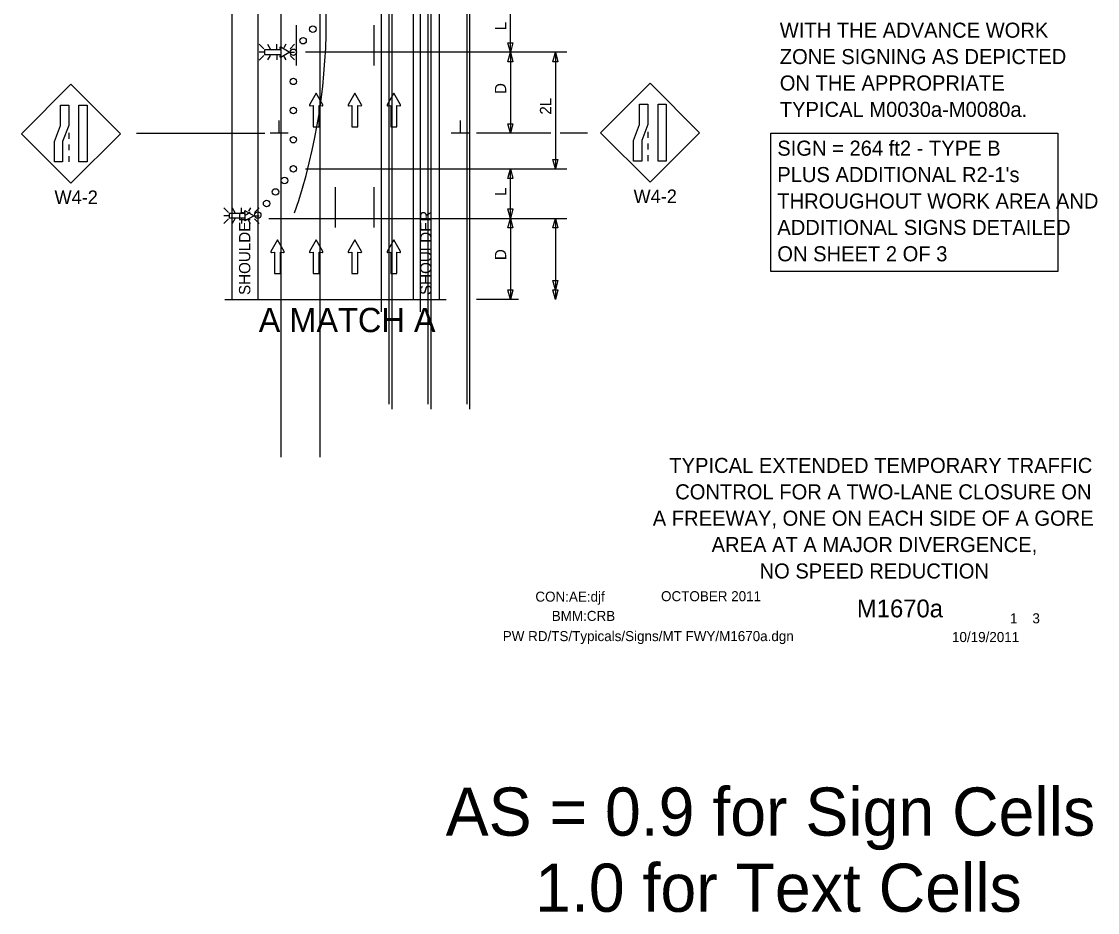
# Model space of a CAD drawing. Extents: x 16715 to 19504, y 7040 to 8495.
# Drawn here: x 16773 to 17438, y 7052 to 7602 of the extents above; entities that cross this region are included whole.
import ezdxf

# ---------------------------------------------------------------- set-up
doc = ezdxf.new("R2010")
doc.units = 0
for name, color, linetype in [('ALI_LEGAL_EX', 7, 'Continuous'), ('BORDER', 7, 'Continuous'), ('BORDER_SIGNAL_WO', 7, 'Continuous'), ('MT_SCRATCH_LEVEL_E', 7, 'Continuous'), ('PAVT_EDGE_EX', 7, 'Continuous'), ('TRAFFIC_SIGNS_PR', 7, 'Continuous'), ('TYPICAL_TEXT_DIMEN_EX', 7, 'Continuous'), ('TYPICAL_TEXT_DIMEN_PR', 7, 'Continuous')]:
    doc.layers.add(name, color=color, linetype=linetype)

msp = doc.modelspace()

# ---------------------------------------------------------------- linework, layer by layer
at = {"layer": 'ALI_LEGAL_EX'}
for p, q in [((16995.53, 8241.3), (16995.53, 7423.16)), ((17019.53, 8241.3), (17019.53, 7423.16)), ((17000.51, 7366.28), (17000.51, 7976.48)), ((17002.26, 7363.06), (17002.26, 7973.25)), ((17024.51, 7366.28), (17024.51, 7976.48)), ((17026.26, 7363.06), (17026.26, 7973.25)), ((17048.51, 7366.28), (17048.51, 7976.48)), ((17050.26, 7363.06), (17050.26, 7973.25)), ((16933.79, 7333.59), (16933.79, 7943.78)), ((16933.79, 7333.59), (16933.79, 7943.78)), ((16957.79, 7333.59), (16957.79, 7943.78))]:
    msp.add_line(p, q, dxfattribs=at)
for points in [[(16943.24, 7575.32), (16943.24, 7600.32)], [(16991.24, 7575.32), (16991.24, 7600.32)], [(16967.24, 7475.32), (16967.24, 7500.32)], [(16991.24, 7475.32), (16991.24, 7500.32)]]:
    msp.add_lwpolyline(points, dxfattribs=at)
msp.add_arc((16597.56, 7601.98), 364, 341.14744, 21.33821, dxfattribs=at)
at = {"layer": 'MT_SCRATCH_LEVEL_E'}
for p, q in [((16955.34, 7558.35), (16951.23, 7551.11)), ((16959.49, 7551.11), (16955.34, 7558.35)), ((16979.24, 7558.35), (16975.13, 7551.11)), ((16983.39, 7551.11), (16979.24, 7558.35)), ((17003.3, 7558.35), (16999.19, 7551.11)), ((17007.44, 7551.11), (17003.3, 7558.35)), ((16951.71, 7550.42), (16953.49, 7550.74)), ((16953.49, 7550.74), (16953.49, 7537.48)), ((16957.23, 7537.48), (16957.23, 7550.74)), ((16957.23, 7550.74), (16959.01, 7550.42)), ((16975.62, 7550.42), (16977.39, 7550.74)), ((16977.39, 7550.74), (16977.39, 7537.48)), ((16981.13, 7537.48), (16981.13, 7550.74)), ((16981.13, 7550.74), (16982.91, 7550.42)), ((16999.67, 7550.42), (17001.44, 7550.74)), ((17001.44, 7550.74), (17001.44, 7537.48)), ((17005.19, 7537.48), (17005.19, 7550.74)), ((17005.19, 7550.74), (17006.96, 7550.42)), ((16953.49, 7537.48), (16957.23, 7537.48)), ((16977.39, 7537.48), (16981.13, 7537.48)), ((17001.44, 7537.48), (17005.19, 7537.48)), ((16931.44, 7467.76), (16927.33, 7460.51)), ((16935.58, 7460.51), (16931.44, 7467.76)), ((16955.34, 7467.76), (16951.23, 7460.51)), ((16959.49, 7460.51), (16955.34, 7467.76)), ((16979.24, 7467.76), (16975.13, 7460.51)), ((16983.39, 7460.51), (16979.24, 7467.76)), ((17003.3, 7467.76), (16999.19, 7460.51)), ((17007.44, 7460.51), (17003.3, 7467.76)), ((16927.81, 7459.83), (16929.58, 7460.15)), ((16929.58, 7460.15), (16929.58, 7446.89)), ((16933.33, 7446.89), (16933.33, 7460.15)), ((16933.33, 7460.15), (16935.1, 7459.83)), ((16951.71, 7459.83), (16953.49, 7460.15)), ((16953.49, 7460.15), (16953.49, 7446.89)), ((16957.23, 7446.89), (16957.23, 7460.15)), ((16957.23, 7460.15), (16959.01, 7459.83)), ((16975.62, 7459.83), (16977.39, 7460.15)), ((16977.39, 7460.15), (16977.39, 7446.89)), ((16981.13, 7446.89), (16981.13, 7460.15)), ((16981.13, 7460.15), (16982.91, 7459.83)), ((16999.67, 7459.83), (17001.44, 7460.15)), ((17001.44, 7460.15), (17001.44, 7446.89)), ((17005.19, 7446.89), (17005.19, 7460.15)), ((17005.19, 7460.15), (17006.96, 7459.83)), ((16929.58, 7446.89), (16933.33, 7446.89)), ((16953.49, 7446.89), (16957.23, 7446.89)), ((16977.39, 7446.89), (16981.13, 7446.89)), ((17001.44, 7446.89), (17005.19, 7446.89))]:
    msp.add_line(p, q, dxfattribs=at)
for centre, start, end in [((16951.64, 7550.88), 150.42484, 279.96381), ((16959.08, 7550.88), 260.03619, 29.77312), ((16975.54, 7550.88), 150.42484, 279.96381), ((16982.98, 7550.88), 260.03619, 29.77312), ((16999.59, 7550.88), 150.42484, 279.96381), ((17007.03, 7550.88), 260.03619, 29.77312), ((16927.73, 7460.29), 150.42484, 279.96381), ((16935.17, 7460.29), 260.03619, 29.77312), ((16951.64, 7460.29), 150.42484, 279.96381), ((16959.08, 7460.29), 260.03619, 29.77312), ((16975.54, 7460.29), 150.42484, 279.96381), ((16982.98, 7460.29), 260.03619, 29.77312), ((16999.59, 7460.29), 150.42484, 279.96381), ((17007.03, 7460.29), 260.03619, 29.77312)]:
    msp.add_arc(centre, 0.463, start, end, dxfattribs=at)
at = {"layer": 'PAVT_EDGE_EX'}
for p, q in [((16903.24, 7785.52), (16903.24, 7430.94)), ((16919.24, 7785.52), (16919.24, 7430.94)), ((17015.24, 7785.52), (17015.24, 7430.94)), ((17031.24, 7785.52), (17031.24, 7430.94))]:
    msp.add_line(p, q, dxfattribs=at)
at = {"layer": 'TRAFFIC_SIGNS_PR'}
for p, q in [((16923.02, 7585.61), (16920.2, 7588.43)), ((16925.32, 7588.43), (16926.94, 7585.61)), ((16931.1, 7585.61), (16931.1, 7588.43)), ((16936.57, 7588.43), (16935.37, 7586.34)), ((16942.01, 7588.43), (16939.19, 7585.61)), ((16923.02, 7583.58), (16920.2, 7583.58)), ((16923.02, 7581.55), (16920.2, 7578.72)), ((16926.97, 7581.55), (16925.34, 7578.73)), ((16931.1, 7581.55), (16931.1, 7578.73)), ((16935.29, 7580.91), (16936.55, 7578.73)), ((16939.19, 7583.58), (16942.01, 7583.58)), ((16942.01, 7578.73), (16939.19, 7581.55)), ((16803.96, 7563.76), (16773.41, 7533.21)), ((16834.5, 7533.21), (16803.96, 7563.76)), ((17161.49, 7564.36), (17130.94, 7533.81)), ((17192.04, 7533.81), (17161.49, 7564.36)), ((16802.55, 7533.76), (16802.55, 7530.16)), ((17130.94, 7533.81), (17161.49, 7503.26)), ((17160.09, 7534.36), (17160.09, 7530.76)), ((17161.49, 7503.26), (17192.04, 7533.81)), ((16773.41, 7533.21), (16803.96, 7502.66)), ((16803.96, 7502.66), (16834.5, 7533.21)), ((17160.09, 7527.16), (17160.09, 7523.56)), ((16802.55, 7526.56), (16802.55, 7522.96)), ((16802.55, 7519.36), (16802.55, 7515.76)), ((17160.09, 7519.96), (17160.09, 7516.36)), ((16901.15, 7484.66), (16898.33, 7487.48)), ((16903.44, 7487.48), (16905.07, 7484.66)), ((16909.23, 7484.66), (16909.23, 7487.48)), ((16914.7, 7487.48), (16913.49, 7485.38)), ((16920.14, 7487.48), (16917.32, 7484.66)), ((16901.15, 7482.62), (16898.33, 7482.62)), ((16901.15, 7480.59), (16898.33, 7477.77)), ((16905.1, 7480.59), (16903.47, 7477.77)), ((16909.23, 7480.59), (16909.23, 7477.77)), ((16917.32, 7482.62), (16920.14, 7482.62)), ((16920.14, 7477.78), (16917.32, 7480.59)), ((16913.41, 7479.96), (16914.67, 7477.77))]:
    msp.add_line(p, q, dxfattribs=at)
for points in [[(16932.93, 7586.26), (16933.16, 7584.96), (16923.44, 7584.96), (16923.44, 7582.22), (16933.16, 7582.22), (16932.93, 7580.92)], [(16933.43, 7580.56), (16938.74, 7583.58), (16933.43, 7586.62)], [(16911.06, 7485.31), (16911.29, 7484.01), (16901.56, 7484.01), (16901.56, 7481.27), (16911.29, 7481.27), (16911.06, 7479.96)], [(16911.56, 7479.61), (16916.87, 7482.62), (16911.56, 7485.67)]]:
    msp.add_lwpolyline(points, dxfattribs=at)
for points in [[(16802.55, 7550.91), (16802.55, 7538.34), (16798.79, 7528.34), (16798.79, 7515.76), (16793.74, 7515.76), (16793.74, 7528.34), (16797.5, 7538.34), (16797.5, 7550.91)], [(16813.96, 7550.91), (16813.96, 7515.76), (16808.9, 7515.76), (16808.9, 7550.91)], [(17160.09, 7551.51), (17160.09, 7538.94), (17156.33, 7528.94), (17156.33, 7516.36), (17151.27, 7516.36), (17151.27, 7528.94), (17155.03, 7538.94), (17155.03, 7551.51)], [(17171.49, 7551.51), (17171.49, 7516.36), (17166.44, 7516.36), (17166.44, 7551.51)]]:
    msp.add_lwpolyline(points, close=True, dxfattribs=at)
for centre in [(16953.24, 7597.79), (16947.24, 7590.65), (16941.24, 7583.51), (16941.24, 7565.51), (16941.24, 7547.51), (16941.24, 7529.51), (16941.24, 7511.51), (16935.75, 7504.37), (16930.25, 7497.25), (16924.75, 7490.12), (16919.25, 7482.99)]:
    msp.add_circle(centre, 2, dxfattribs=at)
for centre, start, end in [((16933.27, 7580.86), 170.73078, 298.89165), ((16933.27, 7586.32), 61.48329, 189.95933), ((16911.39, 7485.37), 61.48329, 189.95933), ((16911.39, 7479.91), 170.73078, 298.89165)]:
    msp.add_arc(centre, 0.341, start, end, dxfattribs=at)
at = {"layer": 'TYPICAL_TEXT_DIMEN_EX'}
msp.add_lwpolyline([(17236.01, 7533.46), (17413.28, 7533.46), (17413.28, 7448.15), (17236.01, 7448.15)], close=True, dxfattribs=at)
at = {"layer": 'TYPICAL_TEXT_DIMEN_PR'}
for p, q in [((17075.24, 7583.51), (17075.24, 7612.07)), ((17075.24, 7583.51), (17073.67, 7589.37)), ((17073.67, 7589.37), (17075.24, 7589.37)), ((17075.24, 7589.37), (17076.81, 7589.37)), ((17076.81, 7589.37), (17075.24, 7583.51)), ((17110.03, 7583.51), (16948.75, 7583.51)), ((17073.67, 7577.64), (17075.24, 7583.51)), ((17075.24, 7583.51), (17075.24, 7533.51)), ((17075.24, 7583.51), (17076.81, 7577.64)), ((17101.48, 7577.64), (17103.05, 7583.51)), ((17103.05, 7583.51), (17104.62, 7577.64)), ((17103.05, 7583.51), (17103.05, 7511.51)), ((17075.24, 7577.64), (17073.67, 7577.64)), ((17076.81, 7577.64), (17075.24, 7577.64)), ((17103.05, 7577.64), (17101.48, 7577.64)), ((17104.62, 7577.64), (17103.05, 7577.64)), ((16932.53, 7533.51), (16932.53, 7541.29)), ((17044.37, 7533.51), (17044.37, 7541.29)), ((17075.24, 7533.51), (17073.67, 7539.37)), ((17073.67, 7539.37), (17075.24, 7539.37)), ((17075.24, 7539.37), (17076.81, 7539.37)), ((17076.81, 7539.37), (17075.24, 7533.51)), ((16844.34, 7533.51), (16923.54, 7533.51)), ((16938.15, 7533.51), (16926.9, 7533.51)), ((17049.99, 7533.51), (17038.74, 7533.51)), ((17100.32, 7533.51), (17054.24, 7533.51)), ((17122.8, 7533.51), (17106.04, 7533.51)), ((17103.05, 7511.51), (17101.48, 7517.37)), ((17101.48, 7517.37), (17103.05, 7517.37)), ((17103.05, 7517.37), (17104.62, 7517.37)), ((17104.62, 7517.37), (17103.05, 7511.51)), ((16948.75, 7511.51), (17110.03, 7511.51)), ((17073.67, 7505.64), (17075.24, 7511.51)), ((17075.24, 7480.94), (17075.24, 7511.51)), ((17075.24, 7511.51), (17076.81, 7505.64)), ((17075.24, 7505.64), (17073.67, 7505.64)), ((17076.81, 7505.64), (17075.24, 7505.64)), ((16926.2, 7480.94), (17110.03, 7480.94)), ((17075.24, 7480.94), (17073.67, 7486.8)), ((17073.67, 7486.8), (17075.24, 7486.8)), ((17073.67, 7475.08), (17075.24, 7480.94)), ((17075.24, 7486.8), (17076.81, 7486.8)), ((17076.81, 7486.8), (17075.24, 7480.94)), ((17075.24, 7480.94), (17075.24, 7430.94)), ((17075.24, 7480.94), (17076.81, 7475.08)), ((17101.48, 7475.08), (17103.05, 7480.94)), ((17103.05, 7480.94), (17103.05, 7430.94)), ((17103.05, 7480.94), (17104.62, 7475.08)), ((17075.24, 7475.08), (17073.67, 7475.08)), ((17076.81, 7475.08), (17075.24, 7475.08)), ((17103.05, 7475.08), (17101.48, 7475.08)), ((17104.62, 7475.08), (17103.05, 7475.08)), ((17103.05, 7436.76), (17101.48, 7442.62)), ((17101.48, 7442.62), (17103.05, 7442.62)), ((17103.05, 7442.62), (17104.62, 7442.62)), ((17104.62, 7442.62), (17103.05, 7436.76)), ((17075.24, 7430.94), (17073.67, 7436.8)), ((17073.67, 7436.8), (17075.24, 7436.8)), ((17075.24, 7436.8), (17076.81, 7436.8)), ((17076.81, 7436.8), (17075.24, 7430.94)), ((17103.05, 7430.94), (17101.48, 7436.8)), ((17101.48, 7436.8), (17103.05, 7436.8)), ((17103.05, 7436.8), (17104.62, 7436.8)), ((17104.62, 7436.8), (17103.05, 7430.94)), ((16898.94, 7430.94), (17035.59, 7430.94)), ((17080.24, 7430.94), (17054.24, 7430.94))]:
    msp.add_line(p, q, dxfattribs=at)

# ---------------------------------------------------------------- texts
at = {"layer": 'BORDER'}
for s, p in [('TYPICAL EXTENDED TEMPORARY TRAFFIC', (17173.38, 7323.77)), ('CONTROL FOR A TWO-LANE CLOSURE ON', (17177.02, 7307.48)), ('A FREEWAY, ONE ON EACH SIDE OF A GORE', (17163.17, 7291.19)), ('AREA AT A MAJOR DIVERGENCE,', (17199.49, 7274.9)), ('NO SPEED REDUCTION', (17229.11, 7258.61))]:
    msp.add_text(s, height=9.3, dxfattribs=at).set_placement(p)
at = {"layer": 'BORDER_SIGNAL_WO'}
for s, height, p in [('CON:AE:djf  ', 6.2, (17090.69, 7244.31)), ('    OCTOBER 2011    ', 6.2, (17159.08, 7244.59)), ('    M1670a   ', 11, (17272.86, 7234.63)), ('BMM:CRB   ', 6.2, (17100.81, 7232.42)), (' 1    3 ', 6.2, (17381.45, 7230.95)), ('PW RD/TS/Typicals/Signs/MT FWY/M1670a.dgn      ', 6.2, (17070.55, 7219.96)), ('10/19/2011    ', 6.2, (17347.93, 7219.38)), ('AS = 0.9 for Sign Cells', 29.7271, (17035.33, 7099.85)), ('     1.0 for Text Cells', 29.7271, (17035.33, 7052.85))]:
    msp.add_text(s, height=height, dxfattribs=at).set_placement(p)
at = {"layer": 'TRAFFIC_SIGNS_PR'}
for p in [(16793.78, 7489.8), (17151.32, 7490.39)]:
    msp.add_text('W4-2', height=8.37, dxfattribs=at).set_placement(p)
at = {"layer": 'TYPICAL_TEXT_DIMEN_EX'}
for s, p in [('WITH THE ADVANCE WORK', (17241.59, 7592.49)), ('ZONE SIGNING AS DEPICTED', (17241.59, 7576.19)), ('ON THE APPROPRIATE', (17241.59, 7559.89)), ('TYPICAL M0030a-M0080a.', (17241.59, 7543.59)), ('SIGN = 264 ft2 - TYPE B', (17240.06, 7519.64)), ("PLUS ADDITIONAL R2-1's", (17240.06, 7503.34)), ('THROUGHOUT WORK AREA AND', (17240.06, 7487.04)), ('ADDITIONAL SIGNS DETAILED', (17240.06, 7470.74)), ('ON SHEET 2 OF 3', (17240.06, 7454.44))]:
    msp.add_text(s, height=9.3, dxfattribs=at).set_placement(p)
at = {"layer": 'TYPICAL_TEXT_DIMEN_PR'}
for s, p in [('L', (17072.78, 7597.14)), ('D', (17072.69, 7557.72)), ('2L', (17100.49, 7545.01)), ('L', (17072.69, 7494.8)), ('SHOULDER', (16914.68, 7433.65)), ('SHOULDER', (17026.54, 7433.65)), ('D', (17072.69, 7455.16))]:
    msp.add_text(s, height=7, rotation=90, dxfattribs=at).set_placement(p)
msp.add_text('A MATCH A', height=15, dxfattribs=at).set_placement((16919.84, 7410.7))

doc.saveas('drawing.dxf')
